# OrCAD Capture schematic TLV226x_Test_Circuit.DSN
size A; title: TLV226x, TLV226xA Advanced LinCMOS RAIL-TO-RAIL; rev: 1.1; note: Datasheet: SLOS186C  EVM: N/A
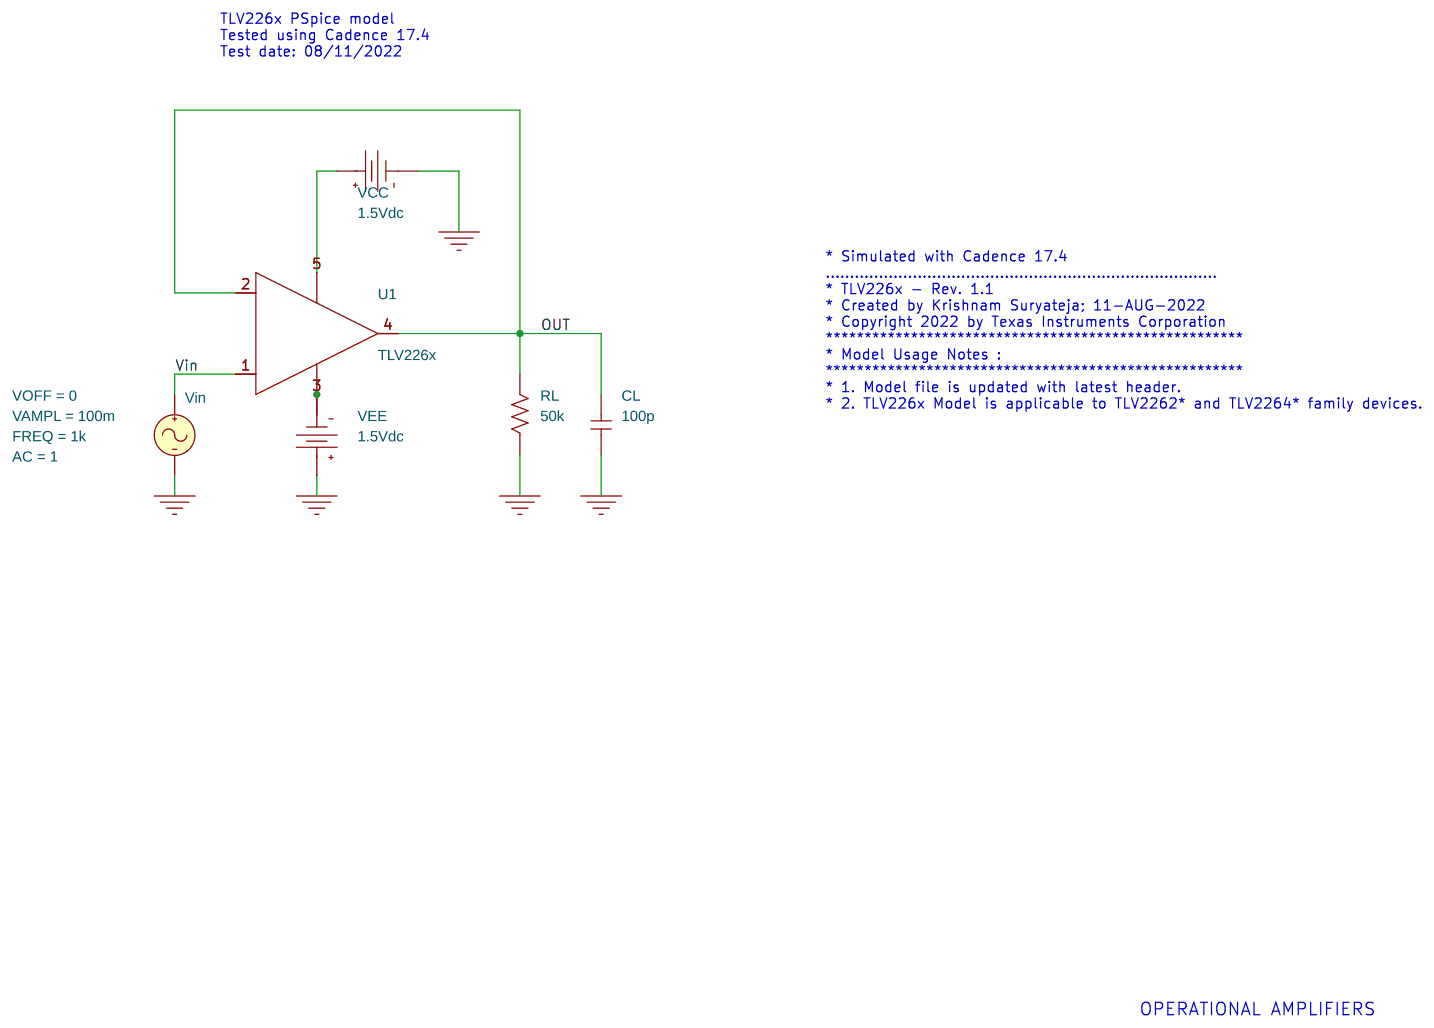
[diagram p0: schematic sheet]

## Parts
CL  100p  [RAD/CK05]
RL  50k  [AX/RC05]
U1  TLV226x
VCC  VDC
VEE  VDC
Vin  VSIN

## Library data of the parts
CL = C
RL = R
U1 = TLV226x
VCC VEE = VDC: DC: 1.5Vdc
Vin = VSIN: AC: 1; FREQ: 1k; VAMPL: 100m; VOFF: 0

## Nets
Vin: U1.1(+) Vin.1(+)
0: CL.1 RL.1 VCC.1(-) VEE.0(+) Vin.2(-)
OUT: CL.2 RL.2 U1.2(-) U1.4(OUT)
N22995: U1.5(V+) VCC.0(+)
N39479: U1.3(V-) VEE.1(-)

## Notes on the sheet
- TLV226x PSpice model
  Tested using Cadence 17.4
  Test date: 08/11/2022
- * Simulated with Cadence 17.4
  .................................................................................
  * TLV226x - Rev. 1.1
  * Created by Krishnam Suryateja; 11-AUG-2022
  * Copyright 2022 by Texas Instruments Corporation
  ******************************************************
  * Model Usage Notes :
  ******************************************************
  * 1. Model file is updated with latest header.
  * 2. TLV226x Model is applicable to TLV2262* and TLV2264* family devices.
- OPERATIONAL AMPLIFIERS
